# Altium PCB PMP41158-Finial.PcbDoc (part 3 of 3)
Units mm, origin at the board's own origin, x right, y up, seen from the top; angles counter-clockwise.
Board outline 125.73 x 87.63 mm, 6 copper layers (Top Layer, Layer 2, Layer 3, Layer 4, Layer 5, Bottom Layer), stack 1.999 mm thick; 200 components, 69 nets, 525 pads, 780 vias.
Unrouted connection lines stored in the file: 16.
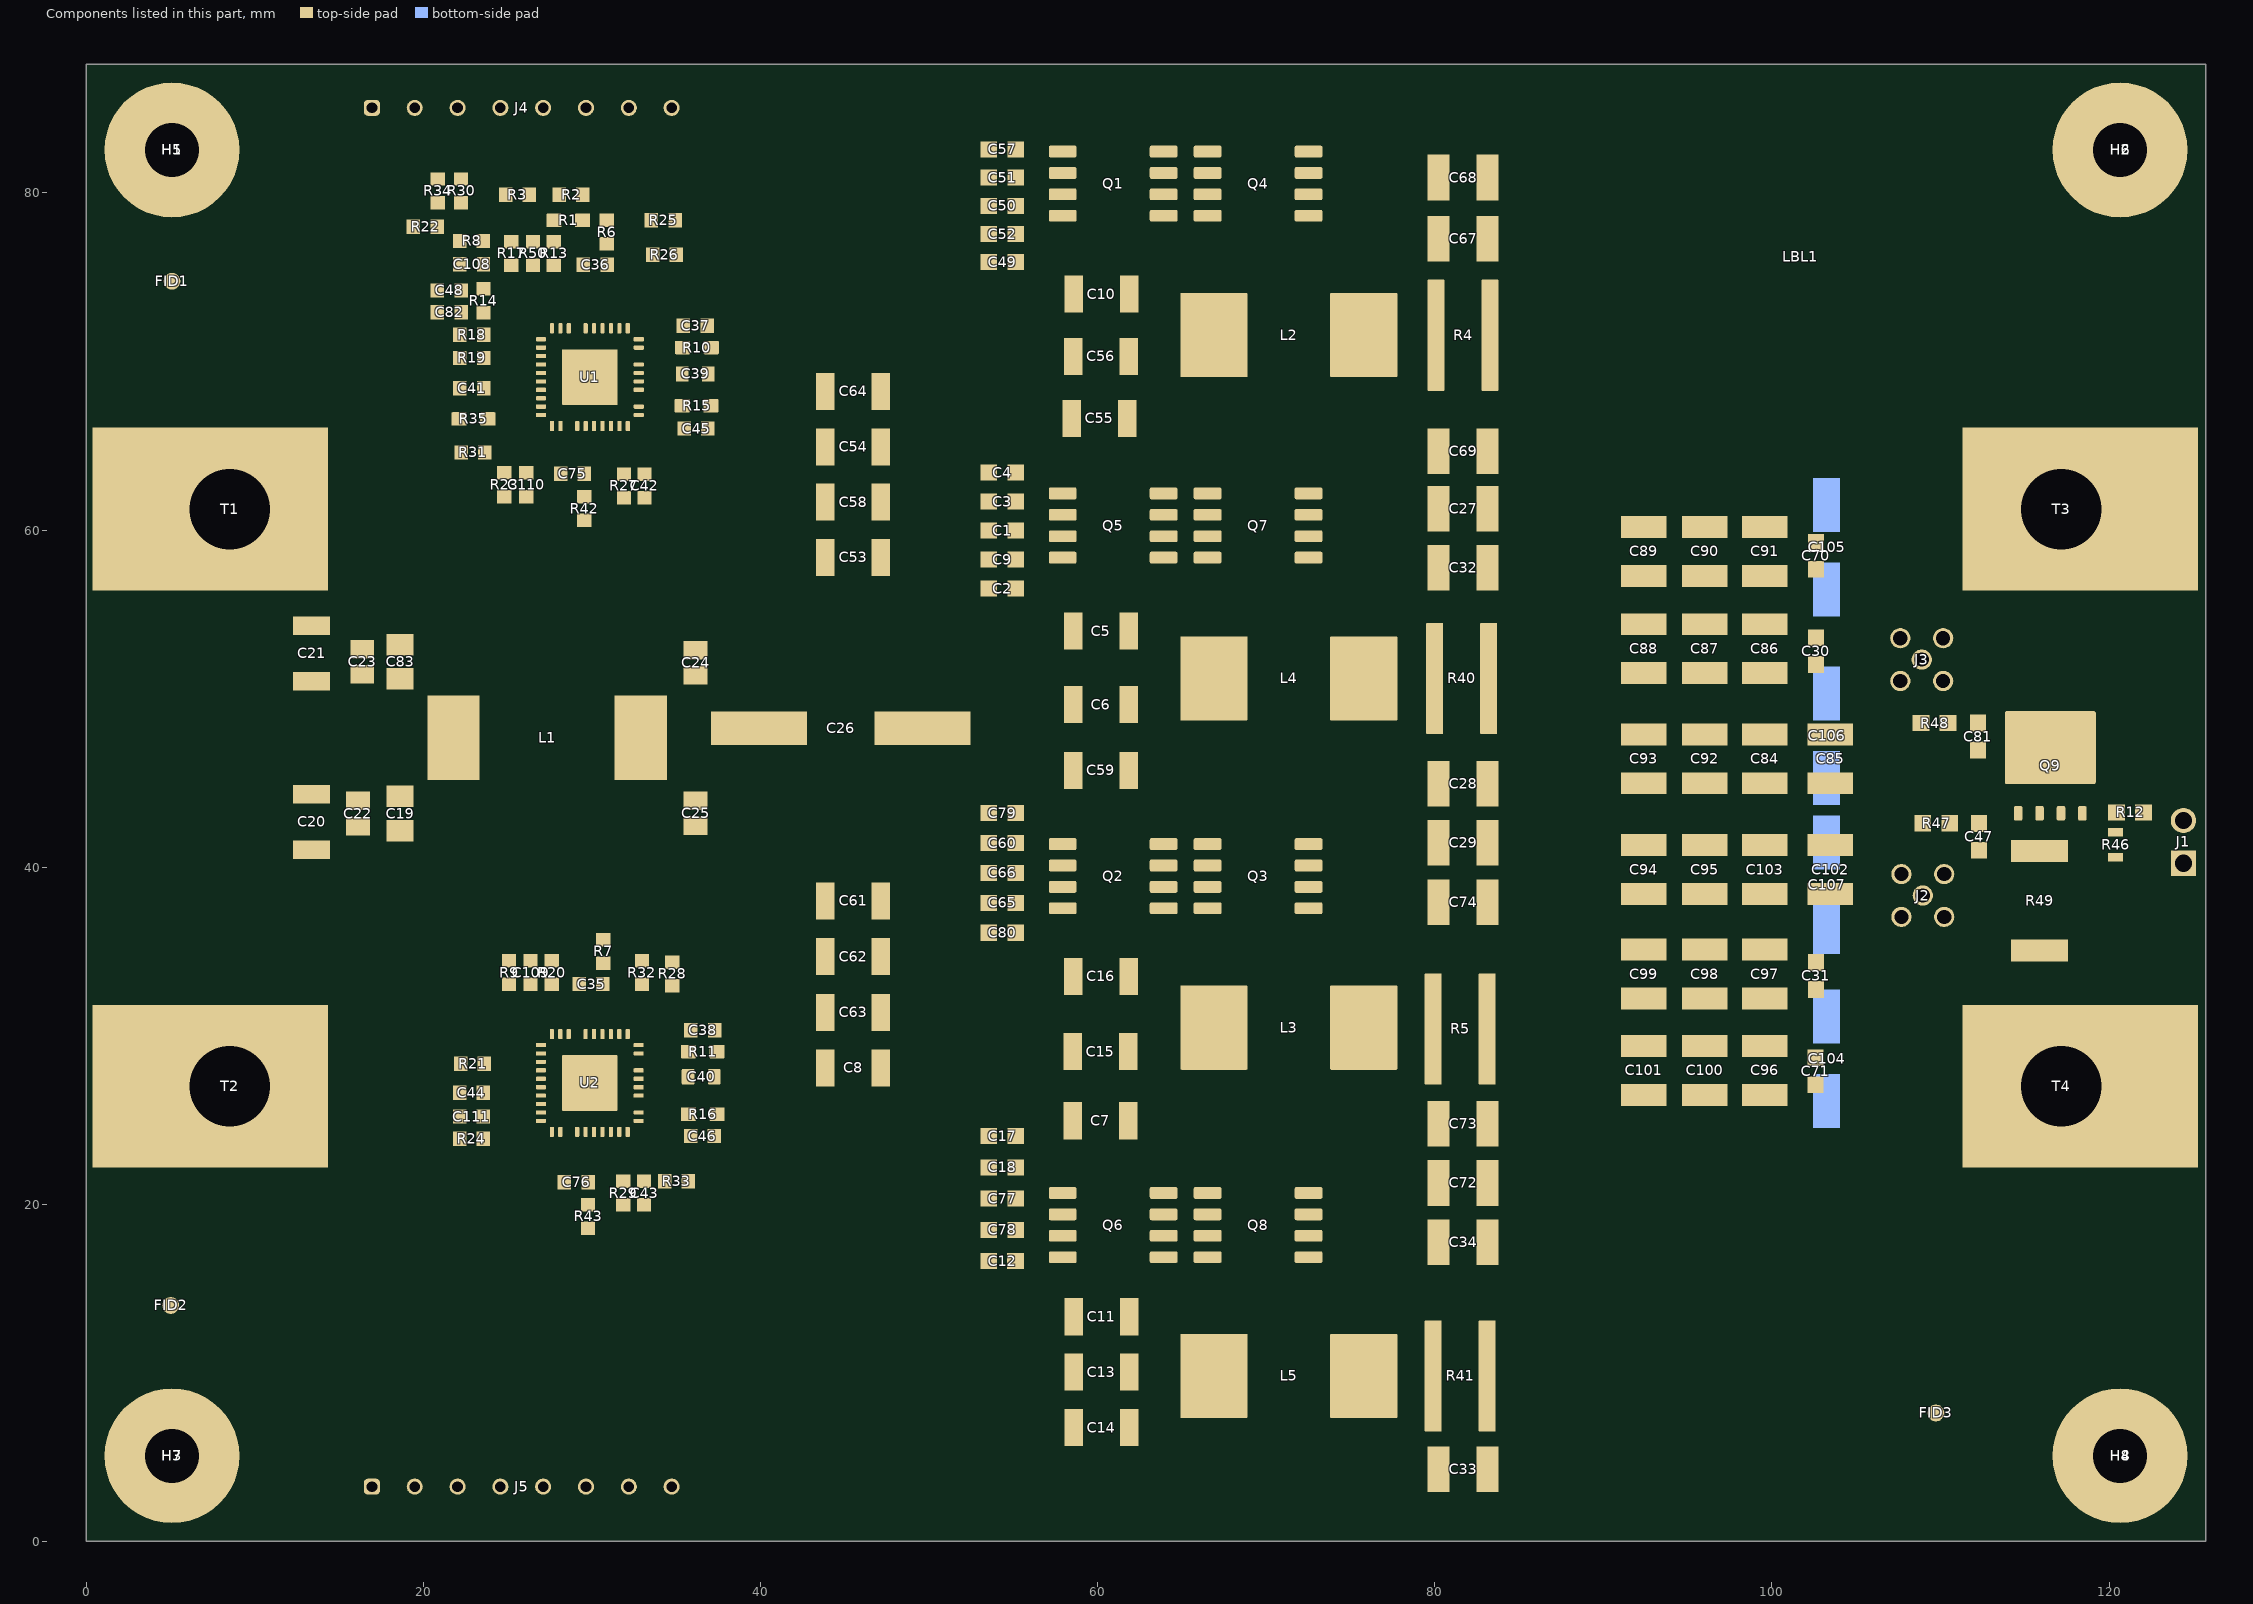
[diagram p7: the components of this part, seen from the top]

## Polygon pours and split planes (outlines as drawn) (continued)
NetC19_1 on Top Layer "TOP_LAYER_NETC19_1_P007" (solid, remove dead copper, pour order 7): 11.25,56.75 14.301,56.75 14.301,65.936 0.25,65.936 0.25,44.757 1.757,43.25 21.716,43.25 23.5,45.034 23.5,51.248 22.618,52.13 11.937,52.13 11.25,52.818
GND on Top Layer "TOP_LAYER_GND_P006" (solid, remove dead copper, pour order 6): 73.319,21.626 74,22.308 74,25.569 74.87,26.439 80.62,26.439 80.864,26.194 80.864,14.701 80.683,14.519 73.183,14.519 71.7,16.002 71.7,21.383 71.943,21.626
GND on Top Layer "TOP_LAYER_GND_P005" (solid, remove dead copper, pour order 5): 73.719,42.324 74,42.605 74,45.701 74.799,46.5 80.695,46.5 80.864,46.331 80.864,34.999 80.683,34.817 73.183,34.817 71.7,36.3 71.7,41.837 72.187,42.324
GND on Top Layer "TOP_LAYER_GND_P004" (solid, remove dead copper, pour order 4): 73.567,63.128 74,63.561 74,65.25 74.988,66.238 80.675,66.238 80.864,66.049 80.864,55.802 80.683,55.621 73.183,55.621 71.7,57.104 71.7,62.641 72.187,63.128
NetC37_1 on Top Layer "TOP_LAYER_NETC37_1_P001" (solid, remove dead copper, pour order 1): 63.069,82.649 63.069,77.937 64.339,76.668 64.339,68.901 68.75,68.901 68.75,75.622 71.25,78.122 71.25,82.651 70.49,83.41 63.83,83.41
NetC47_1 on Layer 2 "LAYER_2_NETC47_1_P049" (solid, remove dead copper, pour order 49): 114,43.785 114.276,44.061 120.533,44.061 120.986,43.608 120.986,39.591 114.276,39.591 114.276,39.624 114,39.9
VOUT1_1 on Layer 2 "LAYER_2_VOUT1_1_P048" (solid, remove dead copper, pour order 48): 111.269,68 111.269,50.745 112.293,49.722 112.293,49.708 113.624,48.376 113.624,44.916 114,44.541 114,44.524 124.44,44.524 125.25,45.334 125.25,68
GND on Layer 2 "LAYER_2_GND_P036" (solid, remove dead copper, pour order 36): 0.962,57.614 0.507,57.159 0.507,41 22.542,41 22.542,52.116 22.978,52.552 49.5,52.552 49.5,57.614
GND on Layer 2 "LAYER_2_GND_P035" (solid, remove dead copper, pour order 35): 10.215,25.302 21.838,36.925 50.413,36.925 50.413,43.052 29.448,43.052 1.835,43.052 0.507,41.724 0.507,25.302
VIN on Layer 2 "LAYER_2_VIN_P034" (solid, remove dead copper, pour order 34): 41.223,43.475 41.701,43.953 41.701,51.171 40.732,52.14 31.466,52.14 31.006,51.68 31.006,44.485 32.017,43.475
GND on Layer 2 "LAYER_2_GND_P027" (solid, remove dead copper, pour order 27): 0.25,79.25 8,87 118,87 125.243,79.757 125.243,70 125.219,70 123.719,68.5 111.25,68.5 111,68.25 111,50.48 113.25,48.23 113.25,39.372 113.662,38.96 123.706,38.96 125.243,37.447 125.243,8.278 117.465,0.5 8.186,0.5 0.5,8.186 0.5,21 1.126,21.626 14.626,21.626 14.931,21.931 14.931,29.382 22.008,36.459 42.237,36.459 42.237,58.155 3.594,58.155 0.25,61.499
VIN on Layer 3 "LAYER_3_VIN_P045" (solid, remove dead copper, pour order 45): 0.25,79.5 7.75,87 34.858,87 35.524,86.334 35.524,61.46 29.315,55.25 29.657,54.907 36.054,61.304 36.054,61.707 36.054,85.804 37.25,87 81.983,87 81.983,0.75 37.25,0.75 36.054,1.946 36.054,32.763 30.783,38.033 30.387,37.637 35.524,32.5 35.524,1.992 34.282,0.75 8.716,0.75 0.25,9.216 0.25,41.434 1.468,42.653 22.149,42.653 24.277,44.781 24.277,51.633 23.018,52.892 12.104,52.892 11.736,53.26 11.736,66 1.231,66 0.25,66.981
NetC19_1 on Layer 3 "LAYER_3_NETC19_1_P033" (solid, remove dead copper, pour order 33): 0.25,66 11.25,66 11.25,52.818 11.937,52.13 22.618,52.13 23.5,51.248 23.5,45.034 21.716,43.25 1.757,43.25 0.25,44.757
VOUT1_1 on Layer 3 "LAYER_3_VOUT1_1_P028" (solid, remove dead copper, pour order 28): 117.445,0.75 117.445,0.804 125.219,8.578 125.219,79.281 117.5,87 93.5,87 93,86.5 93,69.058 95.437,66.621 104.997,66.621 104.997,66.238 95.319,66.238 92.651,68.907 92.651,86.599 92.25,87 82.75,87 82.75,0.75 92.873,0.75 93.129,1.006 93.129,19.973 94.907,21.75 104.997,21.75 104.997,21.355 95.096,21.355 93.522,19.781 93.522,0.987 93.759,0.75
GND on Layer 5 "LAYER_5_GND_P030" (solid, remove dead copper, pour order 30): 82.25,86.099 81.349,87 7.5,87 0.5,80 0.5,67.333 1.147,66.685 11.594,66.685 11.594,53.344 12.437,52.5 19.75,52.5 20.698,51.552 20.698,47.151 20.698,43.545 19.903,42.75 1,42.75 0.5,42.25 0.5,20.328 14.125,20.328 14.394,20.597 14.394,29.456 21.863,36.925 42.237,36.925 42.237,36.459 22.008,36.459 14.931,29.382 14.931,19.931 14.611,19.611 0.899,19.611 0.538,19.25 0.5,19.25 0.5,8 7.75,0.75 82.25,0.75
NetC19_1 on Layer 5 "LAYER_5_NETC19_1_P060" (solid, remove dead copper, pour order 60): 0.25,65.898 11.25,65.898 11.25,52.818 11.937,52.13 19.124,52.13 20.25,51.004 20.25,43.944 19.556,43.25 1.757,43.25 0.25,44.757
VOUT1_1 on Layer 5 "LAYER_5_VOUT1_1_P059" (solid, remove dead copper, pour order 59): 93.5,86.5 107.75,86.5 118.788,75.462 118.788,66.04 119.078,65.75 119.75,65.75 120,66 120,75.735 109.25,86.485 109.25,86.75 109.5,87 117.629,87 125.219,79.409 125.219,8.312 117.658,0.75 93.759,0.75 93.522,0.987 93.522,19.781 95.096,21.355 104.997,21.355 104.997,21.75 94.907,21.75 93.129,19.973 93.129,1.006 92.873,0.75 82.75,0.75 82.75,86.099 83.151,86.5 92.067,86.5 92.651,85.916 92.651,68.907 95.319,66.238 104.997,66.238 104.997,66.621 95.437,66.621 93,69.058 93,86
NetC47_1 on Bottom Layer "BOTTOM_LAYER_NETC47_1_P047" (solid, remove dead copper, pour order 47): 114,43.785 114.276,44.061 120.533,44.061 120.986,43.608 120.986,39.591 114.276,39.591 114.276,39.624 114,39.9
VOUT1_1 on Bottom Layer "BOTTOM_LAYER_VOUT1_1_P046" (solid, remove dead copper, pour order 46): 111.269,68 111.269,50.745 112.293,49.722 112.293,49.708 113.222,49.708 113.624,49.306 113.624,44.916 114,44.541 114,44.524 124.44,44.524 125.25,45.334 125.25,68
GND on Bottom Layer "BOTTOM_LAYER_GND_P038" (solid, remove dead copper, pour order 38): 0.5,8 7.75,0.75 117.673,0.75 125.219,8.297 125.219,9.25 125.219,37.447 123.706,38.96 113.662,38.96 113.25,39.372 113.25,48.23 111,50.48 111,68.25 111.25,68.5 123.719,68.5 125.219,70 125.219,79.252 117.471,87 8,87 0.5,79.5 0.5,60.564 10.4,60.564 12.809,58.155 42.237,58.155 42.237,57.614 12.489,57.614 9.928,60.175 0.5,60.175 0.5,20.328 14.125,20.328 14.394,20.597 14.394,29.456 21.863,36.925 42.237,36.925 42.237,36.459 22.008,36.459 14.931,29.382 14.931,19.931 14.611,19.611 0.899,19.611 0.538,19.25 0.5,19.25
GND on Layer 4 "LAYER_4_GND_P061" (solid, remove dead copper, pour order 61): 0.5,8 7.75,0.75 117.673,0.75 125.219,8.297 125.219,9.25 125.219,37.447 125.219,68.326 125.219,79.252 117.471,87 8,87 0.5,79.5 0.5,60.564 10.4,60.564 12.809,58.155 42.237,58.155 42.237,57.614 12.489,57.614 9.928,60.175 0.5,60.175 0.5,20.328 14.125,20.328 14.394,20.597 14.394,29.456 21.863,36.925 42.237,36.925 42.237,36.459 22.008,36.459 14.931,29.382 14.931,19.931 14.611,19.611 0.899,19.611 0.538,19.25 0.5,19.25

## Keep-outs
Keep-Out Layer:
  text ".Layer_Name" at 14.656,-21.806 h0.9

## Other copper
Top Layer:
  region net GND: 50.5,50.028 51.296,50.824 51.296,64.845 51.756,65.306 53.713,65.306 54.204,64.814 54.204,34.106 53.656,33.558 51.777,33.558 51.296,34.039 51.296,45.859 50.624,46.532 47.37,46.532 46.55,47.352 46.55,49.452 47.127,50.028
  region net GND: 27.09,27.617 27.09,27.279 28.191,27.279 28.191,27.617
  region net GND: 26.987,69.492 26.987,69.154 28.089,69.154 28.089,69.492
  region net GND: 90.23,28.093 89.962,28.362 89.962,32.859 90.344,33.242 105.215,33.242 105.535,32.921 105.535,28.32 105.266,28.051
  region net GND: 90.417,40.614 89.944,41.088 89.944,45.585 90.326,45.967 105.197,45.967 105.517,45.647 105.517,41.046 105.045,40.573
  region net GND: 90.23,53.122 89.962,53.391 89.962,57.888 90.344,58.271 105.215,58.271 105.535,57.95 105.535,53.349 105.266,53.08
  text ".Layer_Name" at 14.656,-21.806 h0.9
Layer 2:
  pour cut-out: 106.779,36.545 106.779,40.094 107.152,40.467 110.84,40.467 111.118,40.189 111.118,36.43 110.88,36.192 107.132,36.192
  pour cut-out: 106.715,50.541 106.715,54.089 107.088,54.463 110.776,54.463 111.054,54.184 111.054,50.426 110.816,50.188 107.068,50.188
Layer 3:
  pour cut-out: 106.779,36.545 106.779,40.094 107.152,40.467 110.84,40.467 111.118,40.189 111.118,36.43 110.88,36.192 107.132,36.192
  pour cut-out: 106.715,50.541 106.715,54.089 107.088,54.463 110.776,54.463 111.054,54.184 111.054,50.426 110.816,50.188 107.068,50.188
  pour cut-out: 51.522,68.772 51.245,68.495 51.245,31.738 51.573,31.41 52.67,31.41 52.868,31.609 52.868,68.508 52.618,68.757
  region net NetC45_1: 63.398,58.114 63.648,57.864 70.569,57.864 70.792,58.088 70.792,62.507 70.476,62.823 65.799,62.823 65.482,62.507 65.482,61.358 65.083,60.959 63.93,60.959 63.922,60.966 63.398,60.441
  region net NetC46_1: 63.469,16.621 63.719,16.371 70.64,16.371 70.864,16.594 70.864,21.014 70.547,21.33 65.87,21.33 65.554,21.014 65.554,19.865 65.154,19.466 64.001,19.466 63.994,19.473 63.469,18.948
  region net NetC38_1: 63.398,37.289 63.648,37.039 70.569,37.039 70.792,37.263 70.792,41.682 70.476,41.998 65.799,41.998 65.482,41.682 65.482,40.533 65.083,40.134 63.93,40.134 63.922,40.141 63.398,39.616
  region net NetC45_1: 63.398,58.114 63.648,57.864 70.569,57.864 70.792,58.088 70.792,62.507 70.476,62.823 65.799,62.823 65.482,62.507 65.482,61.358 65.083,60.959 63.93,60.959 63.922,60.966 63.398,60.441
  region net NetC37_1: 63.398,78.446 63.648,78.196 70.569,78.196 70.792,78.42 70.792,82.839 70.476,83.155 65.799,83.155 65.482,82.839 65.482,81.691 65.083,81.291 63.93,81.291 63.922,81.298 63.398,80.773
Layer 4:
  pour cut-out: 106.779,36.545 106.779,40.094 107.152,40.467 110.84,40.467 111.118,40.189 111.118,36.43 110.88,36.192 107.132,36.192
  pour cut-out: 106.715,50.541 106.715,54.089 107.088,54.463 110.776,54.463 111.054,54.184 111.054,50.426 110.816,50.188 107.068,50.188
Layer 5:
  region net NetC46_1: 63.469,16.621 63.719,16.371 70.64,16.371 70.864,16.594 70.864,21.014 70.547,21.33 65.87,21.33 65.554,21.014 65.554,19.865 65.154,19.466 64.001,19.466 63.994,19.473 63.469,18.948
  region net NetC38_1: 63.398,37.289 63.648,37.039 70.569,37.039 70.792,37.263 70.792,41.682 70.476,41.998 65.799,41.998 65.482,41.682 65.482,40.533 65.083,40.134 63.93,40.134 63.922,40.141 63.398,39.616
  region net NetC45_1: 63.398,58.114 63.648,57.864 70.569,57.864 70.792,58.088 70.792,62.507 70.476,62.823 65.799,62.823 65.482,62.507 65.482,61.358 65.083,60.959 63.93,60.959 63.922,60.966 63.398,60.441
  region net NetC37_1: 63.398,78.446 63.648,78.196 70.569,78.196 70.792,78.42 70.792,82.839 70.476,83.155 65.799,83.155 65.482,82.839 65.482,81.691 65.083,81.291 63.93,81.291 63.922,81.298 63.398,80.773
  pour cut-out: 106.779,36.545 106.779,40.094 107.152,40.467 110.84,40.467 111.118,40.189 111.118,36.43 110.88,36.192 107.132,36.192
  pour cut-out: 106.715,50.541 106.715,54.089 107.088,54.463 110.776,54.463 111.054,54.184 111.054,50.426 110.816,50.188 107.068,50.188
Bottom Layer:
  region net VOUT1_1: 101.234,63.321 105.056,63.321 105.535,62.841 105.535,60.075 105.267,59.807 101.167,59.807 100.875,60.099 100.875,62.962
  region net VOUT1_1: 101.167,52.25 105.119,52.25 105.468,51.901 105.468,47.464 105.129,47.125 101.059,47.125 100.808,47.375 100.808,51.892
  region net VOUT1_1: 101.167,39.367 105.119,39.367 105.468,39.018 105.468,34.581 105.129,34.242 101.059,34.242 100.808,34.492 100.808,39.008
  region net VOUT1_1: 101.234,27.867 105.056,27.867 105.535,27.387 105.535,24.621 105.267,24.353 101.167,24.353 100.875,24.644 100.875,27.508
  pour cut-out: 106.779,36.545 106.779,40.094 107.152,40.467 110.84,40.467 111.118,40.189 111.118,36.43 110.88,36.192 107.132,36.192
  pour cut-out: 106.715,50.541 106.715,54.089 107.088,54.463 110.776,54.463 111.054,54.184 111.054,50.426 110.816,50.188 107.068,50.188
  region net VIN: 56.047,21.125 62.076,21.125 62.222,20.979 62.222,16.612 62.015,16.405 56.038,16.405 55.762,16.681 55.762,20.839
  region net VIN: 55.999,41.889 62.028,41.889 62.173,41.743 62.173,37.376 61.967,37.17 55.989,37.17 55.714,37.445 55.714,41.604
  region net VIN: 55.929,62.635 61.958,62.635 62.104,62.489 62.104,58.122 61.897,57.915 55.92,57.915 55.644,58.191 55.644,62.349
  region net VIN: 55.929,82.917 61.958,82.917 62.104,82.772 62.104,78.404 61.897,78.198 55.92,78.198 55.644,78.473 55.644,82.632
  region net NetC46_1: 63.469,16.621 63.719,16.371 70.64,16.371 70.864,16.594 70.864,21.014 70.547,21.33 65.87,21.33 65.554,21.014 65.554,19.865 65.154,19.466 64.001,19.466 63.994,19.473 63.469,18.948
  region net NetC38_1: 63.398,37.289 63.648,37.039 70.569,37.039 70.792,37.263 70.792,41.682 70.476,41.998 65.799,41.998 65.482,41.682 65.482,40.533 65.083,40.134 63.93,40.134 63.922,40.141 63.398,39.616
  region net NetC45_1: 63.398,58.114 63.648,57.864 70.569,57.864 70.792,58.088 70.792,62.507 70.476,62.823 65.799,62.823 65.482,62.507 65.482,61.358 65.083,60.959 63.93,60.959 63.922,60.966 63.398,60.441
  region net NetC37_1: 63.398,78.446 63.648,78.196 70.569,78.196 70.792,78.42 70.792,82.839 70.476,83.155 65.799,83.155 65.482,82.839 65.482,81.691 65.083,81.291 63.93,81.291 63.922,81.298 63.398,80.773
  text ".Layer_Name" at 14.656,-21.806 h0.9

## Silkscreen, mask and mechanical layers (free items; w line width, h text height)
Top Overlay:
  region: 42.25,43 42.262,43.012 42.262,46.004
  lines w0.15: 13.5,83 16.533,83 16.942,83.346 16.942,84.742 ; 13.622,81.429 17.592,81.423 19.482,83.346 19.482,84.742 ; 15.409,78.398 17.351,78.398 20.839,81.959 26.041,81.959 27.102,82.975 27.102,84.742 ; 15.409,80.05 17.592,80.058 20.292,82.774 24.004,82.783 24.562,83.346 24.562,84.742 ; 32.16,84.641 32.16,82.808 33.275,81.693 36.054,81.693 ; 34.722,84.742 34.722,83.346 35.294,82.774 36.054,82.774
  lines w0.254: 57.922,21.285 57.922,21.626 61.77,21.626 ; 57.922,41.983 57.922,42.324 61.77,42.324 63.988,42.324 63.988,41.983 ; 57.922,62.786 57.922,63.128 61.77,63.128 ; 57.922,83.069 57.922,83.41 61.77,83.41 63.988,83.41 63.988,83.069 ; 57.934,16.233 57.934,15.891 60.406,15.891 64,15.891 64,16.233 ; 57.934,36.931 57.934,36.589 60.406,36.589 64,36.589 64,36.931 ; 57.934,57.734 57.934,57.393 60.406,57.393 64,57.393 64,57.734 ; 57.934,78.017 57.934,77.675 60.406,77.675 64,77.675 64,78.017 ; 61.516,21.626 63.988,21.626 63.988,21.285 ; 61.516,63.128 63.988,63.128 63.988,62.787 ; 66.518,21.285 66.518,21.626 70.367,21.626 72.584,21.626 72.584,21.285 ; 66.518,41.983 66.518,42.324 70.367,42.324 72.584,42.324 72.584,41.983 ; 66.518,62.786 66.518,63.128 70.367,63.128 72.584,63.128 72.584,62.787 ; 66.518,83.069 66.518,83.41 70.367,83.41 72.584,83.41 72.584,83.069 ; 66.531,16.233 66.531,15.891 69.003,15.891 72.597,15.891 72.597,16.233 ; 66.531,36.931 66.531,36.589 69.003,36.589 72.597,36.589 72.597,36.931 ; 66.531,57.734 66.531,57.393 69.003,57.393 72.597,57.393 72.597,57.734 ; 66.531,78.017 66.531,77.675 69.003,77.675 72.597,77.675 72.597,78.017
  text "EN" at 11.299,82.573 h1.52
  text "IMON1" at 36.299,82.398 h1.52
  text "PMP41158A" at 94.699,81.197 h2.75
  text "IMON2" at 36.299,81.151 h1.52
  text "PG" at 11.299,80.91 h1.52
  text "nFLT1" at 11.25,79.538 h1.52
  text "nFLT2" at 11.299,78 h1.52
  text "VOUT+" at 117.467,53.756 h2.54
  text "VIN+" at 1.95,52.622 h2.54
  text "GND" at 2.032,34.224 h2.54
  text "GND" at 118.187,31.042 h2.54
  text "IMON3" at 32.542,5.226 h0.9 r90
  text "IMON4" at 35.082,5.226 h0.9 r90
  text "nFLT3" at 25.041,5.151 h0.9 r90
  text "nFLT4" at 27.462,5.151 h0.9 r90
  text ".Layer_Name" at 14.656,-21.806 h0.9
Bottom Overlay:
  text ".Layer_Name" at 14.656,-21.806 h0.9
Top Paste:
  text ".Layer_Name" at 14.656,-21.806 h0.9
Bottom Paste:
  text ".Layer_Name" at 14.656,-21.806 h0.9
Top Solder:
  text ".Layer_Name" at 14.656,-21.806 h0.9
  text ".Layer_Name" at 14.656,-21.806 h0.9
Bottom Solder:
  rectangle: 44,0.25 97.5,87.75
  text ".Layer_Name" at 14.656,-21.806 h0.9
Drill Guide:
  text ".Layer_Name" at 14.656,-21.806 h0.9
M1 Board Outline:
  the board outline again, w0.254
  text ".Layer_Name" at 14.656,-21.806 h0.9
M2 Board Dimensions:
  rectangle: 0,-6.985 3.175,-3.81
  rectangle: 3.175,-10.16 12.7,-6.985
  lines w0.178: 0,-6.985 25.4,-6.985 ; 3.175,-10.16 3.175,-3.81 ; 6.35,-10.16 6.35,-3.81 ; 12.7,-10.16 12.7,-3.81 ; 19.05,-10.16 19.05,-3.81 ; 0,-10.16 25.4,-10.16 25.4,-3.81 0,-3.81 0,-10.16
  text ".Layer_Name" at 14.656,-21.806 h0.9
M3 3D STEP Top:
  text ".Layer_Name" at 14.656,-21.806 h0.9
M4 3D STEP Bottom:
  text ".Layer_Name" at 14.656,-21.806 h0.9
M5 Assembly Top:
  lines w0.254: -7.417,-23.626 160.223,-23.626 ; -7.417,-18.462 160.274,-18.462 ; -7.417,-13.297 -7.417,-28.791 94.31,-28.791 160.274,-28.791 160.274,-13.297 -7.404,-13.297 -7.404,-28.791 32.614,-28.791 ; 55.194,-28.791 55.194,-13.297 ; 87.376,-18.462 87.376,-13.297 ; 108.712,-18.462 108.712,-13.297 ; 124.511,-28.956 124.511,-23.804
  text "COMPONENTS MARKED 'DNP' SHOULD NOT BE POPULATED." at 29.299,-8.09 h0.9
  text "ASSEMBLY VARIANT:" at 29.286,-11.024 h0.9
  text ".VariantName" at 55.601,-11.024 h0.9
  text "PCB VIEWED FROM TOP SIDE" at -5.804,-16.654 h0.9
  text "BOARD #:" at 57.099,-16.654 h0.9
  text ".PRJ_Number" at 70.955,-16.654 h0.9
  text "REV:" at 92.405,-16.654 h0.9
  text ".PCB_Rev" at 99.809,-16.654 h0.9
  text "SVN REV:" at 113.69,-16.654 h0.9
  text ".VersionControl_RevNumber" at 126.543,-16.654 h0.9
  text "TID #:" at 57.099,-21.819 h0.9
  text ".TID" at 70.955,-21.819 h0.9
  text "PLOT NAME =" at -5.804,-27.034 h0.9
  text ".plot_File_Name" at 14.656,-27.034 h0.9
  text "GENERATED    :" at 57.15,-27.034 h0.9
  text ".Print_Date" at 79.235,-27.034 h0.9
  text ".Print_Time" at 97.752,-27.034 h0.9
  text "TEXAS INSTRUMENTS" at 129.87,-27.034 h0.9
M6 Assembly Bottom:
  lines w0.254: -7.429,-18.474 160.261,-18.474 ; -7.379,-23.639 160.261,-23.639 ; 28.334,-28.969 28.334,-23.817 ; 44.133,-18.474 44.133,-13.31 ; 65.468,-18.474 65.468,-13.31 ; 97.65,-28.804 97.65,-13.31 ; 120.231,-28.804 160.249,-28.804 160.249,-13.31 -7.429,-13.31 -7.429,-28.804 58.534,-28.804 160.261,-28.804 160.261,-13.31
  text "COMPONENTS MARKED 'DNP' SHOULD NOT BE POPULATED." at 154.991,-8.077 h0.9
  text ".VariantName" at 128.473,-11.024 h0.9
  text "ASSEMBLY VARIANT:" at 154.864,-11.024 h0.9
  text ".VersionControl_RevNumber" at 26.302,-16.667 h0.9
  text "SVN REV:" at 39.154,-16.667 h0.9
  text ".PCB_Rev" at 53.035,-16.667 h0.9
  text "REV:" at 60.439,-16.667 h0.9
  text ".PRJ_Number" at 81.89,-16.667 h0.9
  text "BOARD #:" at 95.745,-16.667 h0.9
  text "PCB VIEWED FROM BOTTOM SIDE" at 158.648,-16.667 h0.9
  text ".TID" at 81.89,-21.831 h0.9
  text "TID #:" at 95.745,-21.831 h0.9
  text "TEXAS INSTRUMENTS" at 22.974,-27.047 h0.9
  text ".Print_Time" at 55.093,-27.047 h0.9
  text ".Print_Date" at 73.609,-27.047 h0.9
  text "GENERATED    :" at 95.694,-27.047 h0.9
  text ".plot_File_Name" at 138.189,-27.047 h0.9
  text "PLOT NAME =" at 158.648,-27.047 h0.9
M9 Title Sheet:
  drawing of 57 lines, arcs and shapes, not listed
  text "1" at 18.792,204.127 h1.78
  text "2" at 82.182,204.127 h1.78
  text "3" at 145.411,204.127 h1.78
  text "4" at 209.08,204.127 h1.78
  text "5" at 272.555,204.127 h1.78
  text "6" at 336.182,204.127 h1.78
  text "A" at -10.579,175.095 h1.78
  text "A" at 365.341,175.095 h1.78
  text "B" at -10.579,114.643 h1.78
  text "B" at 365.341,114.643 h1.78
  text "C" at -10.579,54.318 h1.78
  text "C" at 365.341,54.318 h1.78
  text "PROJECT TITLE:" at 288.125,7.048 h1.14
  text ".PRJ_Title" at 289.395,3.662 h1.78
  text "DESIGNED FOR:" at 288.125,-0.597 h1.14
  text ".PRJ_Customer" at 289.395,-4.153 h1.78
  text "D" at -10.579,-5.88 h1.78
  text "D" at 365.341,-5.88 h1.78
  text "FILE NAME:" at 288.125,-8.217 h1.14
  text ".PCB_File_Name_No_Path" at 289.395,-11.265 h1.78
  text "Texas Instruments (TI) and/or its licensors do not warrant the accuracy or completeness of this specification" at 161.9,-15.376 h1.14
  text "ENGINEER:" at 288.125,-15.583 h1.14
  text "LAYOUT BY:" at 326.352,-15.583 h1.14
  text "or any information contained therein. TI and/or its licensors do not warrant that this design will meet" at 160.757,-18.237 h1.14
  text ".PRJ_Engineer" at 289.395,-19.52 h1.78
  text ".PCB_Layout" at 327.635,-19.52 h1.78
  text "the specifications, will be suitable for your application or fit for any particular purpose, or will operate in" at 160.757,-21.099 h1.14
  text ".Layer_Name" at 14.656,-21.806 h0.9
  text "ALTIUM DESIGNER VERSION:" at 326.352,-23.457 h1.14
  text "an implementation. TI and/or its licensors do not warrant that the design is production worthy. You should" at 160.757,-23.961 h1.14
  text "completely validate and test your design implementation to confirm the system functionality for your application." at 161.9,-26.822 h1.14
  text ".print_Scale" at 289.395,-26.843 h1.78
  text ".Application_BuildNumber" at 327.635,-26.843 h1.78
  text "1" at 18.792,-32.093 h1.78
  text "2" at 82.182,-32.093 h1.78
  text "3" at 145.411,-32.093 h1.78
  text "4" at 209.08,-32.093 h1.78
  text "5" at 272.555,-32.093 h1.78
  text "6" at 336.182,-32.093 h1.78
M10 Fab Notes:
  drawing of 189 lines, arcs and shapes, not listed
  text "DESIGN INFORMATION" at 314.503,161.447 h0.9
  text "MIN. TRACK WIDTH:" at 298.131,158.091 h0.9
  text "8" at 325.976,158.091 h0.9
  text "MIL" at 329.907,158.091 h0.9
  text "7.874" at 321.75,155 h0.9
  text "MIN. CLEARANCE:" at 298.131,154.938 h0.9
  text "MIL" at 329.907,154.938 h0.9
  text "MIN. VIA PAD SIZE:" at 298.131,151.785 h0.9
  text "24" at 325.214,151.785 h0.9
  text "MIL" at 329.907,151.785 h0.9
  text "0.05mm (2MIL)" at 315.784,148.486 h0.9
  text "MINIMUM ANNULAR RING" at 289.769,148.277 h0.9
  text "EXTERNAL" at 333.768,148.277 h0.9
  text "PER" at 294.849,145.48 h0.9
  text "IPC-D-275 CLASS 2 LEVEL C" at 300.437,145.48 h0.9
  text "MIL, HOLES" at 338.238,142.928 h0.9
  text "+/-" at 328.27,142.709 h0.9
  text "+/-" at 349.961,142.709 h0.9
  text "REGISTRATION TOLERANCES:" at 289.769,142.682 h0.9
  text "METAL" at 320.243,142.682 h0.9
  text "5" at 334.879,142.683 h0.9
  text "3" at 356.037,142.683 h0.9
  text "MIL" at 358.99,142.682 h0.9
  text "HOLE SIZE TOLERANCE (UNLESS OTHERWISE SPECIFIED):" at 289.769,140.185 h0.9
  text "+/-" at 349.961,140.112 h0.9
  text "3" at 356.037,140.085 h0.9
  text "MIL" at 358.99,140.085 h0.9
  text "MATERIAL:" at 287.87,136.589 h0.9
  text "FR-4 High Tg" at 312.926,133.324 h0.9
  text "X" at 309.257,133.122 h0.9
  text "FR-4" at 298.563,133.007 h0.9
  text "OTHER" at 336.358,133.007 h0.9
  text "62 MIL (1.6mm) +/-10%" at 306.694,129.374 h0.9
  text "X" at 303.643,129.312 h0.9
  text "THICKNESS:" at 289.769,129.165 h0.9
  text "OTHER" at 339.33,129.165 h0.9
  text "TOLERANCE:" at 289.769,125.652 h0.9
  text "X" at 311.314,125.652 h0.9
  text "ANSI IPC-6012 TYPE 3 CLASS 2" at 315.836,125.652 h0.9
  text "OTHER +/-" at 315.835,121.989 h0.9
  text "BOW & TWIST:" at 289.769,118.302 h0.9
  text "X" at 311.314,118.302 h0.9
  text "ANSI IPC-6012 TYPE 3 CLASS 2" at 315.836,118.302 h0.9
  text "OTHER +/-" at 315.835,114.576 h0.9
  text "DRILLING:" at 287.87,111.258 h0.9
  text "NC_DRILL FILES" at 332.599,108.586 h0.9
  text "REFERENCE:" at 289.769,108.486 h0.9
  text "X" at 306.463,108.484 h0.9
  text "AS SHOWN" at 310.984,108.486 h0.9
  text "X" at 329.348,108.486 h0.9
  text "OTHER" at 340.168,104.873 h0.9
  text "PTH COPPER THICKNESS:" at 289.761,104.783 h0.9
  text "X" at 318.697,104.783 h0.9
  text "20-30 um" at 321.948,104.783 h0.9
  text "BOARD FINISH:" at 287.87,101.034 h0.9
  text "SILKSCREEN:" at 291.812,98.237 h0.9
  text "X" at 316.14,98.237 h0.9
  text "TOP" at 319.112,98.237 h0.9
  text "X" at 329.094,98.237 h0.9
  text "BOTTOM" at 332.091,98.237 h0.9
  text "SILKSCREEN COLOR:" at 291.812,94.295 h0.9
  text "X" at 316.115,94.295 h0.9
  text "WHITE" at 319.112,94.295 h0.9
  text "OTHER" at 332.091,94.295 h0.9
  text "X" at 319.442,90.652 h0.9
  text "GREEN" at 322.439,90.652 h0.9
  text "OTHER" at 338.136,90.652 h0.9
  text "SOLDER RESIST COLOR:" at 291.812,90.477 h0.9
  text "X" at 319.442,86.734 h0.9
  text "MATTE" at 322.439,86.734 h0.9
  text "SEMI-GLOSS" at 338.125,86.717 h0.9
  text "IMMERSION GOLD (ENIG)" at 314.819,82.345 h0.9
  text "ENEPIG" at 348.793,82.162 h0.9
  text "SURFACE FINISH:" at 287.87,82.136 h0.9
  text "X" at 310.298,82.136 h0.9
  text "IMM. TIN/SILVER OR EQUIV" at 296.24,78.649 h0.9
  text "OTHER" at 332.599,78.549 h0.9
  text "ARRAY/PANEL:" at 287.87,74.602 h0.9
  text "CUT AND TRIM PER M1 BOARD OUTLINE" at 314.819,74.393 h0.9
  text "N.C. ROUTE" at 314.819,70.94 h0.9
  text "X" at 332.295,70.94 h0.9
  text "V. SCORE" at 336.816,70.94 h0.9
  text "CERTIFICATION:" at 287.87,67.66 h0.9
  text "MATERIALS AND WORKMANSHIP FOR ALL PCBS" at 306.285,67.66 h0.9
  text "TO MEET OR EXCEED THE REQUIREMENTS OF:" at 306.285,65.271 h0.9
  text "X" at 297.078,62.003 h0.9
  text "ANSI IPC-A-600F CLASS ->" at 300.329,62.003 h0.9
  text "X" at 342.188,62.003 h0.9
  text "2" at 344.982,62.003 h0.9
  text "1" at 336.981,61.965 h0.9
  text "3" at 353.973,61.965 h0.9
  text "X" at 317.702,58.252 h0.9
  text "RoHS" at 320.953,58.252 h0.9
  text "OTHER" at 337.321,58.252 h0.9
  text "PER ORDER" at 347.407,58.252 h0.9
  text "ALL BOARDS MUST MEET OR EXCEED UL94-V0 REQUIREMENTS." at 288.569,54.345 h0.9
  text "PCB MUST BEAR THE UL94V-0 UL REGISTERED MATERIAL ID NUMBER" at 288.569,51.397 h0.9
  text "ADDITIONAL REQUIREMENTS:" at 287.87,47.094 h0.9
  text "MICROSECTION:" at 289.769,44.373 h0.9
  text "YES" at 312.775,44.373 h0.9
  text "REQUIRED" at 334.657,40.707 h0.9
  text "BARE BOARD ELEC. TEST:" at 289.769,40.634 h0.9
  text "NONE" at 322.935,40.634 h0.9
  text "X" at 331.66,40.634 h0.9
  text "PER ORDER" at 349.693,40.634 h0.9
  text "XX MIL VIAS REQUIRE NON-CONDUCTIVE FILL AND PLANARIZE" at 294.04,35.428 h1.5
  text "XX MIL VIAS REQUIRE CONDUCTIVE FILL AND PLANARIZE" at 294.243,32.787 h0.9
  text "OUTER XX MIL TRACES REQUIRE 50 OHM SINGLE-ENDED IMPEDANCE" at 294.218,28.637 h1.47
  text "LAYER 2 & 3 (INNER LAYERS) XX MIL WIDE, XX MIL SPACE / TRACES REQUIRE 100 OHM DIFFERENTIAL IMPEDANCE" at 294.015,22.65 h0.9
  text ".Layer_Name" at 14.656,-21.806 h0.9
M11 Gerber Information:
  lines w0.254: -7.417,-23.626 160.223,-23.626 ; -7.417,-18.462 160.274,-18.462 ; -7.417,-13.297 -7.417,-28.791 94.31,-28.791 160.274,-28.791 160.274,-13.297 -7.404,-13.297 -7.404,-28.791 32.614,-28.791 ; 55.194,-28.791 55.194,-13.297 ; 87.376,-18.462 87.376,-13.297 ; 108.712,-18.462 108.712,-13.297 ; 124.511,-28.956 124.511,-23.804
  text "ALL ARTWORK VIEWED FROM TOP SIDE" at -5.804,-16.654 h0.9
  text "BOARD #:" at 57.099,-16.654 h0.9
  text ".PRJ_Number" at 70.955,-16.654 h0.9
  text "REV:" at 92.405,-16.654 h0.9
  text ".PCB_Rev" at 99.809,-16.654 h0.9
  text "SVN REV:" at 113.69,-16.654 h0.9
  text ".VersionControl_RevNumber" at 126.543,-16.654 h0.9
  text "LAYER NAME =" at -5.804,-21.806 h0.9
  text "TID #:" at 57.099,-21.819 h0.9
  text ".TID" at 70.955,-21.819 h0.9
  text "PLOT NAME =" at -5.804,-27.034 h0.9
  text ".plot_File_Name" at 14.656,-27.034 h0.9
  text "GENERATED    :" at 57.15,-27.034 h0.9
  text ".Print_Date" at 79.235,-27.034 h0.9
  text ".Print_Time" at 97.752,-27.034 h0.9
  text "TEXAS INSTRUMENTS" at 129.87,-27.034 h0.9
M12 Stackup:
  drawing of 399 lines, arcs and shapes, not listed
  text "Layer" at 248.845,200.959 h0.9
  text "Name" at 255.201,200.959 h0.9
  text "Material" at 269.355,200.959 h0.9
  text "Thickness" at 282.46,200.959 h0.9
  text "Constant" at 292.415,200.959 h0.9
  text "Board Layer Stack" at 301.171,200.959 h0.9
  text "Top Overlay" at 255.201,199.16 h0.9
  text "Top Solder" at 255.201,197.36 h0.9
  text "Solder Resist" at 269.355,197.36 h0.9
  text "0.40mil" at 282.46,197.36 h0.9
  text "3.5" at 292.415,197.36 h0.9
  text "1" at 248.845,195.56 h0.9
  text "Top Layer" at 255.201,195.56 h0.9
  text "1.40mil" at 282.46,195.56 h0.9
  text "Dielectric 1" at 255.201,193.76 h0.9
  text "PP-006" at 269.355,193.76 h0.9
  text "2.80mil" at 282.46,193.76 h0.9
  text "4.1" at 292.415,193.76 h0.9
  text "2" at 248.845,191.96 h0.9
  text "Layer 2" at 255.201,191.96 h0.9
  text "CF-004" at 269.355,191.96 h0.9
  text "1.38mil" at 282.46,191.96 h0.9
  text "Dielectric 3" at 255.201,190.16 h0.9
  text "PP-006" at 269.355,190.16 h0.9
  text "2.80mil" at 282.46,190.16 h0.9
  text "4.1" at 292.415,190.16 h0.9
  text "3" at 248.845,188.36 h0.9
  text "Layer 3" at 255.201,188.36 h0.9
  text "CF-004" at 269.355,188.36 h0.9
  text "1.38mil" at 282.46,188.36 h0.9
  text "Dielectric1" at 255.201,186.56 h0.9
  text "FR-4 High Tg" at 269.355,186.56 h0.9
  text "59.20mil" at 282.46,186.56 h0.9
  text "4.8" at 292.415,186.56 h0.9
  text "4" at 248.845,184.76 h0.9
  text "Layer 4" at 255.201,184.76 h0.9
  text "CF-004" at 269.355,184.76 h0.9
  text "1.38mil" at 282.46,184.76 h0.9
  text "Dielectric 4" at 255.201,182.96 h0.9
  text "PP-006" at 269.355,182.96 h0.9
  text "2.80mil" at 282.46,182.96 h0.9
  text "4.1" at 292.415,182.96 h0.9
  text "5" at 248.845,181.16 h0.9
  text "Layer 5" at 255.201,181.16 h0.9
  text "CF-004" at 269.355,181.16 h0.9
  text "1.38mil" at 282.46,181.16 h0.9
  text "Dielectric 2" at 255.201,179.36 h0.9
  text "PP-006" at 269.355,179.36 h0.9
  text "2.80mil" at 282.46,179.36 h0.9
  text "4.1" at 292.415,179.36 h0.9
  text "6" at 248.845,177.56 h0.9
  text "Bottom Layer" at 255.201,177.56 h0.9
  text "1.40mil" at 282.46,177.56 h0.9
  text "Bottom Solder" at 255.201,175.76 h0.9
  text "Solder Resist" at 269.355,175.76 h0.9
  text "0.40mil" at 282.46,175.76 h0.9
  text "3.5" at 292.415,175.76 h0.9
  text "Bottom Overlay" at 255.201,173.96 h0.9
  text ".Layer_Name" at 14.656,-21.806 h0.9
M13 Component Bodies Top:
  text ".Layer_Name" at 14.656,-21.806 h0.9
M14 Component Bodies Bottom:
  text ".Layer_Name" at 14.656,-21.806 h0.9
M15 Courtyards Top:
  text ".Layer_Name" at 14.656,-21.806 h0.9
M16 Courtyards Bottom:
  text ".Layer_Name" at 14.656,-21.806 h0.9
Drill Drawing:
  circle w0.254: c135.694,71.415 r0.5
  lines w0.254: 135.194,68.915 135.444,68.915 135.444,68.665 135.944,68.665 135.944,68.915 136.194,68.915 136.194,69.415 135.944,69.415 135.944,69.665 135.444,69.665 135.444,69.415 135.194,69.415 135.194,68.915 ; 135.194,73.165 136.194,73.165 136.194,74.165 135.194,74.165 135.194,73.165 ; 135.194,75.665 135.444,75.665 135.694,75.415 135.944,75.665 136.194,75.665 135.944,75.915 136.194,76.165 135.944,76.165 135.694,76.415 135.444,76.165 135.194,76.165 135.444,75.915 135.194,75.665 ; 135.194,77.665 136.194,77.665 136.194,78.665 135.194,78.665 135.194,77.665 ; 135.194,80.415 135.694,79.915 136.194,80.415 135.694,80.915 135.194,80.415 ; 135.194,82.165 135.194,82.415 135.444,82.665 135.194,82.915 135.194,83.165 135.444,83.165 135.694,82.915 135.944,83.165 136.194,83.165 136.194,82.915 135.944,82.665 136.194,82.415 136.194,82.165 135.944,82.165 135.694,82.415 135.444,82.165 135.194,82.165 ; 135.194,85.415 136.194,85.415 135.694,84.415 135.194,85.415 ; 135.394,77.865 135.994,77.865 135.994,78.465 135.394,78.465 135.394,77.865
  lines w0.305: 134.264,67.99 232.473,67.99 ; 134.264,85.99 232.473,85.99 ; 142.86,65.74 142.86,88.24 ; 152.761,65.74 152.761,88.24 ; 173.278,65.74 173.278,88.24 ; 181.198,65.74 181.198,88.24 ; 192.538,65.74 192.538,88.24 ; 215.24,65.74 215.24,88.24 ; 134.264,65.74 232.473,65.74 232.473,88.24 134.264,88.24 134.264,65.74
  text "Symbol" at 135.614,86.665 h1.08
  text "Quantity" at 143.535,86.665 h1.08
  text "Finished Hole Size" at 153.436,86.665 h1.08
  text "Plated" at 173.953,86.665 h1.08
  text "Hole Type" at 181.873,86.665 h1.08
  text "Drill Layer Pair" at 193.213,86.665 h1.08
  text "Hole Tolerance" at 215.915,86.665 h1.08
  text "160" at 143.535,84.415 h0.9
  text "7.87mil (0.200mm)" at 153.436,84.415 h0.9
  text "PTH" at 173.953,84.415 h0.9
  text "Round" at 181.873,84.415 h0.9
  text "Top Layer - Bottom Layer" at 193.213,84.415 h0.9
  text "112" at 143.535,82.165 h0.9
  text "16.00mil (0.406mm)" at 153.436,82.165 h0.9
  text "PTH" at 173.953,82.165 h0.9
  text "Round" at 181.873,82.165 h0.9
  text "Top Layer - Bottom Layer" at 193.213,82.165 h0.9
  text "508" at 143.535,79.915 h0.9
  text "19.69mil (0.500mm)" at 153.436,79.915 h0.9
  text "PTH" at 173.953,79.915 h0.9
  text "Round" at 181.873,79.915 h0.9
  text "Top Layer - Bottom Layer" at 193.213,79.915 h0.9
  text "16" at 143.535,77.665 h0.9
  text "25.00mil (0.635mm)" at 153.436,77.665 h0.9
  text "PTH" at 173.953,77.665 h0.9
  text "Round" at 181.873,77.665 h0.9
  text "Top Layer - Bottom Layer" at 193.213,77.665 h0.9
  text "10" at 143.535,75.415 h0.9
  text "33.07mil (0.840mm)" at 153.436,75.415 h0.9
  text "PTH" at 173.953,75.415 h0.9
  text "Round" at 181.873,75.415 h0.9
  text "Top Layer - Bottom Layer" at 193.213,75.415 h0.9
  text "2" at 143.535,73.165 h0.9
  text "40.16mil (1.020mm)" at 153.436,73.165 h0.9
  text "PTH" at 173.953,73.165 h0.9
  text "Round" at 181.873,73.165 h0.9
  text "Top Layer - Bottom Layer" at 193.213,73.165 h0.9
  text "4" at 143.535,70.915 h0.9
  text "125.98mil (3.200mm)" at 153.436,70.915 h0.9
  text "PTH" at 173.953,70.915 h0.9
  text "Round" at 181.873,70.915 h0.9
  text "Top Layer - Bottom Layer" at 193.213,70.915 h0.9
  text "4" at 143.535,68.665 h0.9
  text "188.00mil (4.775mm)" at 153.436,68.665 h0.9
  text "PTH" at 173.953,68.665 h0.9
  text "Round" at 181.873,68.665 h0.9
  text "Top Layer - Bottom Layer" at 193.213,68.665 h0.9
  text "816 Total" at 143.535,66.415 h0.9
  text ".Layer_Name" at 14.656,-21.806 h0.9
M17 Embedded Cavity:
  text ".Layer_Name" at 14.656,-21.806 h0.9
M18 Embedded Assembly:
  text ".Layer_Name" at 14.656,-21.806 h0.9
M19 Embedded Keepout:
  text ".Layer_Name" at 14.656,-21.806 h0.9

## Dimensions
0,-10.16 to 25.4,-10.16 on M2 Board Dimensions
0,0 to 0,87.63 on M2 Board Dimensions
0,0 to 125.73,0 on M2 Board Dimensions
